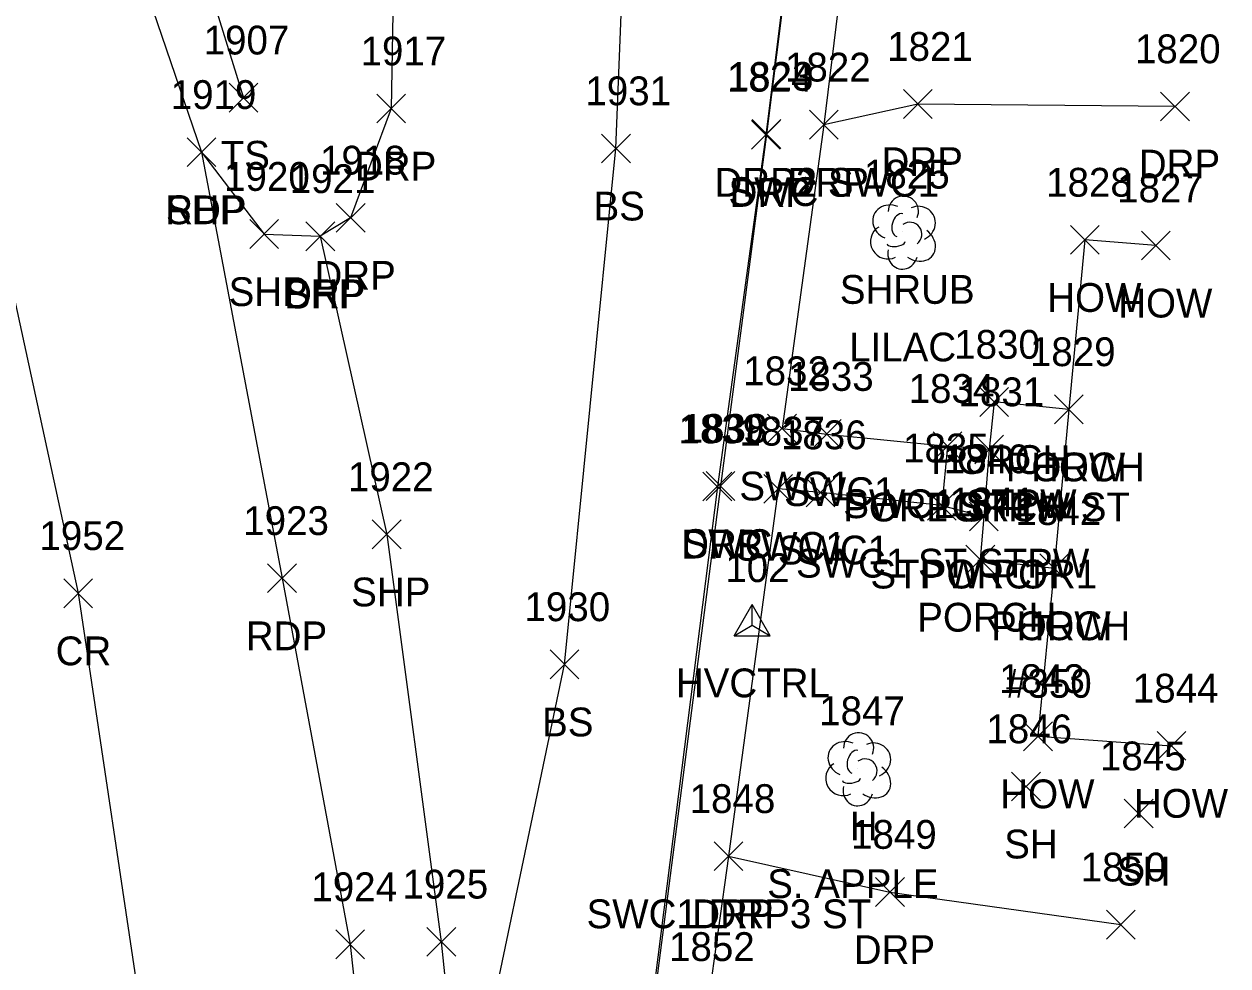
# Model space of a CAD drawing. Extents: x 1651305 to 1654558, y 539481 to 548441.
# Drawn here: x 1654376.5 to 1654460.1, y 544479.5 to 544544.9 of the extents above; entities that cross this region are included whole.
import ezdxf

# ---------------------------------------------------------------- set-up
doc = ezdxf.new("R2010")
doc.units = 0
for name, color, linetype in [('C_A', 7, 'Continuous'), ('C_I', 7, 'Continuous'), ('CPSM', 7, 'Continuous'), ('L_A', 7, 'Continuous'), ('L_C', 7, 'Continuous'), ('L_I', 7, 'Continuous'), ('L_TIC', 7, 'Continuous'), ('LBC', 7, 'Continuous'), ('LBF', 7, 'Continuous'), ('LELB', 7, 'Continuous'), ('LSH', 7, 'Continuous'), ('LTD', 7, 'Continuous'), ('P_A', 7, 'Continuous'), ('P_I', 7, 'Continuous'), ('P_TIC', 7, 'Continuous'), ('PET', 7, 'Continuous'), ('PRC', 7, 'Continuous'), ('PSP', 7, 'Continuous'), ('R_A', 7, 'Continuous'), ('R_I', 7, 'Continuous'), ('R_TIC', 7, 'Continuous'), ('RDP', 7, 'Continuous'), ('RSW', 7, 'Continuous')]:
    doc.layers.add(name, color=color, linetype=linetype)

msp = doc.modelspace()

# ---------------------------------------------------------------- linework, layer by layer
at = {"layer": 'CPSM'}
for p, q in [((1654425.791, 544502.445), (1654427.041, 544504.61)), ((1654428.291, 544502.445), (1654427.041, 544504.61)), ((1654427.041, 544503.166), (1654427.041, 544504.61)), ((1654425.791, 544502.445), (1654427.041, 544503.166)), ((1654427.041, 544503.166), (1654427.041, 544503.166)), ((1654427.041, 544503.166), (1654428.291, 544502.445)), ((1654425.791, 544502.445), (1654428.291, 544502.445))]:
    msp.add_line(p, q, dxfattribs=at)
at = {"layer": 'L_TIC'}
for points in [[(1654390.723, 544538.804), (1654392.723, 544540.804)], [(1654392.723, 544538.804), (1654390.723, 544540.804)], [(1654416.578, 544535.277), (1654418.578, 544537.277)], [(1654418.578, 544535.277), (1654416.578, 544537.277)], [(1654449.131, 544528.931), (1654451.131, 544530.931)], [(1654451.131, 544528.931), (1654449.131, 544530.931)], [(1654454.057, 544528.54), (1654456.057, 544530.54)], [(1654456.057, 544528.54), (1654454.057, 544530.54)], [(1654442.837, 544517.674), (1654444.837, 544519.674)], [(1654444.837, 544517.674), (1654442.837, 544519.674)], [(1654448.013, 544517.162), (1654450.013, 544519.162)], [(1654450.013, 544517.162), (1654448.013, 544519.162)], [(1654448.013, 544517.162), (1654450.013, 544519.162)], [(1654450.013, 544517.162), (1654448.013, 544519.162)], [(1654439.587, 544514.607), (1654441.587, 544516.607)], [(1654441.587, 544514.607), (1654439.587, 544516.607)], [(1654442.484, 544514.378), (1654444.484, 544516.378)], [(1654444.484, 544514.378), (1654442.484, 544516.378)], [(1654442.484, 544514.378), (1654444.484, 544516.378)], [(1654444.484, 544514.378), (1654442.484, 544516.378)], [(1654439.199, 544510.478), (1654441.199, 544512.478)], [(1654441.199, 544510.478), (1654439.199, 544512.478)], [(1654442.114, 544509.723), (1654444.114, 544511.723)], [(1654444.114, 544509.723), (1654442.114, 544511.723)], [(1654442.114, 544509.723), (1654444.114, 544511.723)], [(1654444.114, 544509.723), (1654442.114, 544511.723)], [(1654441.869, 544506.726), (1654443.869, 544508.726)], [(1654443.869, 544506.726), (1654441.869, 544508.726)], [(1654447, 544506.133), (1654449, 544508.133)], [(1654449, 544506.133), (1654447, 544508.133)], [(1654447, 544506.133), (1654449, 544508.133)], [(1654449, 544506.133), (1654447, 544508.133)], [(1654413.004, 544499.453), (1654415.004, 544501.453)], [(1654415.004, 544499.453), (1654413.004, 544501.453)], [(1654445.874, 544494.46), (1654447.874, 544496.46)], [(1654447.874, 544494.46), (1654445.874, 544496.46)], [(1654455.147, 544493.801), (1654457.147, 544495.801)], [(1654457.147, 544493.801), (1654455.147, 544495.801)], [(1654445.039, 544490.975), (1654447.039, 544492.975)], [(1654447.039, 544490.975), (1654445.039, 544492.975)], [(1654452.867, 544489.094), (1654454.867, 544491.094)], [(1654454.867, 544489.094), (1654452.867, 544491.094)]]:
    msp.add_lwpolyline(points, dxfattribs=at)
at = {"layer": 'LBC'}
msp.add_lwpolyline([(1654455.057, 544529.54), (1654450.131, 544529.931), (1654449.013, 544518.162), (1654448, 544507.133), (1654446.874, 544495.46), (1654456.147, 544494.801)], dxfattribs=at)
at = {"layer": 'LBF'}
for points in [[(1654449.013, 544518.162), (1654443.837, 544518.674), (1654443.484, 544515.378), (1654443.114, 544510.723), (1654442.869, 544507.726), (1654448, 544507.133)], [(1654443.484, 544515.378), (1654440.587, 544515.607), (1654440.199, 544511.478), (1654443.114, 544510.723)]]:
    msp.add_lwpolyline(points, dxfattribs=at)
at = {"layer": 'LELB'}
for points in [[(1654406.951, 544466.687), (1654414.004, 544500.453), (1654417.578, 544536.277), (1654418.757, 544565.929), (1654410.195, 544609.107), (1654409.857, 544614.549), (1654405.7, 544641.925)], [(1654360.198, 544631.754), (1654372.116, 544599.924), (1654382.811, 544567.633), (1654386.584, 544556.384), (1654391.723, 544539.804)]]:
    msp.add_lwpolyline(points, dxfattribs=at)
at = {"layer": 'LSH'}
msp.add_line((1654437.485, 544530.491), (1654437.485, 544530.491), dxfattribs=at)
msp.add_line((1654437.485, 544530.491), (1654437.485, 544530.491), dxfattribs=at)
msp.add_arc((1654437.531, 544531.925), 1.047, 335.52715, 180.95627, dxfattribs=at)
for centre, major_axis, ratio, start_param, end_param in [((1654436.693, 544531.157), (1.21, -0.512), 0.895232, 1.570796, 4.712389), ((1654438.526, 544531.074), (-1.141, -0.483), 0.949671, 1.570796, 4.712389), ((1654437.276, 544530.949), (-0.208, -0.792), 0.645439, 3.141593, 6.283185), ((1654436.401, 544529.782), (0.584, -1.042), 0.959034, 3.141593, 6.283185), ((1654437.985, 544530.324), (-0.5, 0.667), 0.989748, 3.141593, 6.283185), ((1654438.485, 544529.658), (-1.09, 0.792), 0.841452, 1.570796, 4.712389), ((1654437.485, 544528.991), (0.265, 1.061), 0.942809, 1.570796, 4.712389), ((1654437.026, 544529.741), (-0.625, -0.083), 0.423636, 0, 3.141593)]:
    msp.add_ellipse(centre, major_axis=major_axis, ratio=ratio, start_param=start_param, end_param=end_param, dxfattribs=at)
at = {"layer": 'LTD'}
msp.add_line((1654434.376, 544493.224), (1654434.376, 544493.224), dxfattribs=at)
msp.add_line((1654434.376, 544493.224), (1654434.376, 544493.224), dxfattribs=at)
msp.add_arc((1654434.423, 544494.657), 1.047, 335.52715, 180.95627, dxfattribs=at)
for centre, major_axis, ratio, start_param, end_param in [((1654433.584, 544493.89), (1.21, -0.512), 0.895232, 1.570796, 4.712389), ((1654435.418, 544493.807), (-1.141, -0.483), 0.949671, 1.570796, 4.712389), ((1654434.168, 544493.682), (-0.208, -0.792), 0.645439, 3.141593, 6.283185), ((1654434.876, 544493.057), (-0.5, 0.667), 0.989748, 3.141593, 6.283185), ((1654433.293, 544492.515), (0.584, -1.042), 0.959034, 3.141593, 6.283185), ((1654435.376, 544492.39), (-1.09, 0.792), 0.841452, 1.570796, 4.712389), ((1654433.918, 544492.473), (-0.625, -0.083), 0.423636, 0, 3.141593), ((1654434.376, 544491.724), (0.265, 1.061), 0.942809, 1.570796, 4.712389)]:
    msp.add_ellipse(centre, major_axis=major_axis, ratio=ratio, start_param=start_param, end_param=end_param, dxfattribs=at)
at = {"layer": 'P_TIC'}
for points in [[(1654387.798, 544535.019), (1654389.798, 544537.019)], [(1654389.798, 544535.019), (1654387.798, 544537.019)], [(1654387.798, 544535.019), (1654389.798, 544537.019)], [(1654389.798, 544535.019), (1654387.798, 544537.019)], [(1654392.152, 544529.334), (1654394.152, 544531.334)], [(1654394.152, 544529.334), (1654392.152, 544531.334)], [(1654396.052, 544529.18), (1654398.052, 544531.18)], [(1654398.052, 544529.18), (1654396.052, 544531.18)], [(1654400.661, 544508.48), (1654402.661, 544510.48)], [(1654402.661, 544508.48), (1654400.661, 544510.48)], [(1654393.392, 544505.433), (1654395.392, 544507.433)], [(1654395.392, 544505.433), (1654393.392, 544507.433)], [(1654379.244, 544504.389), (1654381.244, 544506.389)], [(1654381.244, 544504.389), (1654379.244, 544506.389)], [(1654398.121, 544480.008), (1654400.121, 544482.008)], [(1654400.121, 544480.008), (1654398.121, 544482.008)], [(1654404.45, 544480.191), (1654406.45, 544482.191)], [(1654406.45, 544480.191), (1654404.45, 544482.191)]]:
    msp.add_lwpolyline(points, dxfattribs=at)
at = {"layer": 'PET'}
msp.add_lwpolyline([(1654345.042, 544588.36), (1654350.59, 544607.191), (1654356.582, 544624.309), (1654366.692, 544597.705), (1654378.699, 544565.627), (1654388.798, 544536.019), (1654394.392, 544506.433), (1654399.121, 544481.008), (1654401.125, 544462.893), (1654401.531, 544436.346), (1654401.825, 544421.309), (1654397.366, 544359.696), (1654394.392, 544336.586), (1654391.404, 544308.963), (1654388.941, 544290.736), (1654386.845, 544274.06), (1654380.974, 544229.445), (1654377.749, 544202.908), (1654375.628, 544181.037), (1654372.192, 544149.754), (1654366.612, 544105.723), (1654362.798, 544072.788)], dxfattribs=at)
at = {"layer": 'PRC'}
msp.add_lwpolyline([(1654350.59, 544607.191), (1654355.931, 544592.699), (1654363.685, 544570.628), (1654372.223, 544542.272), (1654380.244, 544505.389), (1654384.95, 544473.916), (1654386.821, 544433.75), (1654385.713, 544395.522), (1654383.86, 544365.997), (1654380.919, 544339.646), (1654377.996, 544311.086), (1654373.889, 544274.842), (1654369.008, 544231.012), (1654366.63, 544212.463), (1654362.444, 544177.974), (1654359.488, 544151.886), (1654354.071, 544107.932), (1654348.42, 544063.008)], dxfattribs=at)
at = {"layer": 'PSP'}
msp.add_lwpolyline([(1654388.798, 544536.019), (1654393.152, 544530.334), (1654397.052, 544530.18), (1654401.661, 544509.48), (1654405.45, 544481.191), (1654406.951, 544466.687), (1654404.923, 544436.226), (1654404.117, 544420.923), (1654397.366, 544359.696)], dxfattribs=at)
at = {"layer": 'R_TIC'}
for points in [[(1654400.972, 544538.048), (1654402.972, 544540.048)], [(1654402.972, 544538.048), (1654400.972, 544540.048)], [(1654437.527, 544538.362), (1654439.527, 544540.362)], [(1654439.527, 544538.362), (1654437.527, 544540.362)], [(1654455.385, 544538.195), (1654457.385, 544540.195)], [(1654457.385, 544538.195), (1654455.385, 544540.195)], [(1654427.025, 544536.281), (1654429.025, 544538.281)], [(1654429.025, 544536.281), (1654427.025, 544538.281)], [(1654431.002, 544536.927), (1654433.002, 544538.927)], [(1654433.002, 544536.927), (1654431.002, 544538.927)], [(1654431.002, 544536.927), (1654433.002, 544538.927)], [(1654433.002, 544536.927), (1654431.002, 544538.927)], [(1654426.975, 544536.224), (1654428.975, 544538.224)], [(1654428.975, 544536.224), (1654426.975, 544538.224)], [(1654398.157, 544530.466), (1654400.157, 544532.466)], [(1654400.157, 544530.466), (1654398.157, 544532.466)], [(1654396.052, 544529.18), (1654398.052, 544531.18)], [(1654398.052, 544529.18), (1654396.052, 544531.18)], [(1654428.103, 544515.836), (1654430.103, 544517.836)], [(1654430.103, 544515.836), (1654428.103, 544517.836)], [(1654431.209, 544515.446), (1654433.209, 544517.446)], [(1654433.209, 544515.446), (1654431.209, 544517.446)], [(1654439.587, 544514.607), (1654441.587, 544516.607)], [(1654441.587, 544514.607), (1654439.587, 544516.607)], [(1654423.616, 544511.8), (1654425.616, 544513.8)], [(1654425.616, 544511.8), (1654423.616, 544513.8)], [(1654423.833, 544511.838), (1654425.833, 544513.838)], [(1654425.833, 544511.838), (1654423.833, 544513.838)], [(1654427.832, 544511.647), (1654429.832, 544513.647)], [(1654429.832, 544511.647), (1654427.832, 544513.647)], [(1654430.777, 544511.392), (1654432.777, 544513.392)], [(1654432.777, 544511.392), (1654430.777, 544513.392)], [(1654439.199, 544510.478), (1654441.199, 544512.478)], [(1654441.199, 544510.478), (1654439.199, 544512.478)], [(1654424.384, 544486.13), (1654426.384, 544488.13)], [(1654426.384, 544486.13), (1654424.384, 544488.13)], [(1654424.384, 544486.13), (1654426.384, 544488.13)], [(1654426.384, 544486.13), (1654424.384, 544488.13)], [(1654435.597, 544483.645), (1654437.597, 544485.645)], [(1654437.597, 544483.645), (1654435.597, 544485.645)], [(1654451.621, 544481.378), (1654453.621, 544483.378)], [(1654453.621, 544481.378), (1654451.621, 544483.378)]]:
    msp.add_lwpolyline(points, dxfattribs=at)
at = {"layer": 'RDP'}
for points in [[(1654389.401, 544756.56), (1654387.7, 544737.059), (1654385.299, 544704.988), (1654383.543, 544677.638), (1654384.483, 544660.968), (1654386.242, 544638.223), (1654391.022, 544611.182), (1654397.72, 544578.233), (1654402.202, 544552.331), (1654401.972, 544539.048), (1654399.157, 544531.466), (1654397.052, 544530.18)], [(1654432.453, 544721.26), (1654412.473, 544723.068), (1654409.324, 544720.532), (1654406.192, 544714.273), (1654402.612, 544671.581), (1654403.27, 544666.414), (1654406.853, 544662.099), (1654407.381, 544661.789), (1654407.089, 544658.718), (1654407.855, 544657.75), (1654443.015, 544654.447), (1654438.677, 544619.923), (1654433.469, 544580.157), (1654430.086, 544554.066), (1654427.975, 544537.224), (1654424.616, 544512.8), (1654419.649, 544473.553), (1654406.951, 544466.687)], [(1654456.385, 544539.195), (1654438.527, 544539.362), (1654432.002, 544537.927)], [(1654425.384, 544487.13), (1654436.597, 544484.645), (1654452.621, 544482.378)]]:
    msp.add_lwpolyline(points, dxfattribs=at)
at = {"layer": 'RSW'}
for points in [[(1654407.404, 544661.775), (1654428.256, 544659.691), (1654428.758, 544663.459), (1654433.255, 544663.27), (1654433.16, 544659.367), (1654447.415, 544658.156), (1654442.622, 544619.191), (1654446.363, 544618.839), (1654446.1, 544614.473), (1654442.009, 544614.425), (1654437.441, 544579.484), (1654433.815, 544552.684), (1654432.002, 544537.927), (1654429.103, 544516.836), (1654432.209, 544516.446), (1654440.587, 544515.607)], [(1654407.404, 544661.775), (1654407.293, 544658.868), (1654407.962, 544657.877), (1654443.269, 544654.592), (1654438.81, 544619.894), (1654433.558, 544580.17), (1654430.136, 544553.995), (1654428.025, 544537.281), (1654424.833, 544512.838), (1654419.77, 544473.615), (1654412.659, 544419.662), (1654404.122, 544354.774), (1654402.102, 544339.773), (1654395.487, 544286.058), (1654394.013, 544276.122), (1654388.386, 544229.583), (1654383.891, 544196.376), (1654382.201, 544184.333), (1654378.352, 544149.148), (1654372.361, 544105.495), (1654368.546, 544072.052)], [(1654440.199, 544511.478), (1654431.777, 544512.392), (1654428.832, 544512.647), (1654425.384, 544487.13), (1654423.952, 544476.853), (1654420.985, 544453.407), (1654434.323, 544452.087)]]:
    msp.add_lwpolyline(points, dxfattribs=at)

# ---------------------------------------------------------------- texts
at = {"layer": 'C_A'}
msp.add_text('HVCTRL', height=2, dxfattribs=at).set_placement((1654421.734, 544498.166))
at = {"layer": 'C_I'}
msp.add_text('102', height=2, dxfattribs=at).set_placement((1654425.167, 544506.166))
at = {"layer": 'L_A'}
for s, p in [('TS', (1654390.133, 544534.804)), ('BS', (1654416.019, 544531.277)), ('SHRUB', (1654433.115, 544525.491)), ('HOW', (1654447.517, 544524.931)), ('HOW', (1654452.443, 544524.54)), ('PORCH', (1654439.46, 544513.674)), ('PORCH', (1654444.635, 544513.162)), ('HOW', (1654446.399, 544513.162)), ('SWC1 STPW', (1654433.359, 544510.607)), ('POR1 STPW ST', (1654433.35, 544510.378)), ('PORCH', (1654439.106, 544510.378)), ('SWC1 ST STPW', (1654430.073, 544506.478)), ('STPW POR1', (1654435.24, 544505.723)), ('PORCH', (1654438.736, 544505.723)), ('PORCH', (1654438.491, 544502.726)), ('PORCH', (1654443.622, 544502.133)), ('HOW', (1654445.386, 544502.133)), ('BS', (1654412.445, 544495.453)), ('HOW', (1654444.26, 544490.46)), ('HOW', (1654453.533, 544489.801)), ('H', (1654433.809, 544488.224)), ('SH', (1654444.527, 544486.975)), ('SH', (1654452.355, 544485.094))]:
    msp.add_text(s, height=2, dxfattribs=at).set_placement(p)
at = {"layer": 'L_C'}
for s, p in [('LILAC', (1654433.76, 544521.491)), ('#350', (1654444.654, 544498.133)), ('S. APPLE', (1654428.077, 544484.224))]:
    msp.add_text(s, height=2, dxfattribs=at).set_placement(p)
at = {"layer": 'L_I'}
for s, p in [('1907', (1654388.952, 544542.804)), ('1931', (1654415.452, 544539.277)), ('1825', (1654434.792, 544533.491)), ('1828', (1654447.439, 544532.931)), ('1827', (1654452.365, 544532.54)), ('1830', (1654441.058, 544521.674)), ('1829', (1654446.313, 544521.162)), ('1829', (1654446.313, 544521.162)), ('1834', (1654437.894, 544518.607)), ('1831', (1654441.358, 544518.378)), ('1831', (1654441.358, 544518.378)), ('1835', (1654437.506, 544514.478)), ('1840', (1654440.335, 544513.723)), ('1840', (1654440.335, 544513.723)), ('1841', (1654440.743, 544510.726)), ('1842', (1654445.308, 544510.133)), ('1842', (1654445.308, 544510.133)), ('1930', (1654411.225, 544503.453)), ('1843', (1654444.181, 544498.46)), ('1844', (1654453.454, 544497.801)), ('1847', (1654431.683, 544496.224)), ('1846', (1654443.291, 544494.975)), ('1845', (1654451.174, 544493.094))]:
    msp.add_text(s, height=2, dxfattribs=at).set_placement(p)
at = {"layer": 'P_A'}
for s, p in [('SHP', (1654386.334, 544531.019)), ('RDP', (1654386.286, 544531.019)), ('SHP', (1654390.687, 544525.334)), ('SHP', (1654394.588, 544525.18)), ('SHP', (1654399.196, 544504.48)), ('RDP', (1654391.881, 544501.433)), ('CR', (1654378.677, 544500.389))]:
    msp.add_text(s, height=2, dxfattribs=at).set_placement(p)
at = {"layer": 'P_I'}
for s, p in [('1919', (1654386.665, 544539.019)), ('1919', (1654386.665, 544539.019)), ('1920', (1654390.372, 544533.334)), ('1921', (1654394.926, 544533.18)), ('1922', (1654398.968, 544512.48)), ('1923', (1654391.7, 544509.433)), ('1952', (1654377.552, 544508.389)), ('1924', (1654396.429, 544484.008)), ('1925', (1654402.757, 544484.191))]:
    msp.add_text(s, height=2, dxfattribs=at).set_placement(p)
at = {"layer": 'R_A'}
for s, p in [('DRP', (1654399.46, 544534.048)), ('DRP', (1654436.015, 544534.362)), ('DRP', (1654453.873, 544534.195)), ('DRP2 SWC1', (1654424.411, 544532.927)), ('DRP', (1654429.49, 544532.927)), ('SWC', (1654425.388, 544532.281)), ('DRP', (1654425.463, 544532.224)), ('DRP', (1654396.645, 544526.466)), ('DRP', (1654394.54, 544525.18)), ('SWC1', (1654426.142, 544511.836)), ('SWC1', (1654429.249, 544511.446)), ('SWC1 STPW', (1654433.359, 544510.607)), ('SWC', (1654422.195, 544507.838)), ('DRP', (1654422.104, 544507.8)), ('SWC1', (1654425.871, 544507.647)), ('SWC1', (1654428.816, 544507.392)), ('SWC1 ST STPW', (1654430.073, 544506.478)), ('SWC1 DRP3 ST', (1654415.534, 544482.13)), ('DRP', (1654422.872, 544482.13)), ('DRP', (1654434.085, 544479.645))]:
    msp.add_text(s, height=2, dxfattribs=at).set_placement(p)
at = {"layer": 'R_I'}
for s, p in [('1821', (1654436.401, 544542.362)), ('1820', (1654453.606, 544542.195)), ('1917', (1654399.846, 544542.048)), ('1822', (1654429.309, 544540.927)), ('1822', (1654429.309, 544540.927)), ('1824', (1654425.282, 544540.224)), ('1823', (1654425.333, 544540.281)), ('1918', (1654397.031, 544534.466)), ('1921', (1654394.926, 544533.18)), ('1832', (1654426.41, 544519.836)), ('1833', (1654429.517, 544519.446)), ('1834', (1654437.894, 544518.607)), ('1839', (1654421.915, 544515.8)), ('1838', (1654422.14, 544515.838)), ('1837', (1654426.139, 544515.647)), ('1836', (1654429.029, 544515.392)), ('1835', (1654437.506, 544514.478)), ('1848', (1654422.691, 544490.13)), ('1848', (1654422.691, 544490.13)), ('1849', (1654433.897, 544487.645)), ('1850', (1654449.842, 544485.378)), ('1852', (1654421.259, 544479.853)), ('1852', (1654421.259, 544479.853))]:
    msp.add_text(s, height=2, dxfattribs=at).set_placement(p)

doc.saveas('drawing.dxf')
